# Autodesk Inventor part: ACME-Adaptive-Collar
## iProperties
Company: ACME-Hardware
Shininess: 64.0
Length Units: 11269
Angle Units: 11279
Time Units: 11290
Mass Units: 11283
Length Display Precision: 3
Angle Display Precision: 2
Compacted: True
Part Number: ACME-Adaptive-Collar
Document SubType Name: Modeling
Created: 2003-12
Catalog Web Link: www.autodesk.com
Vendor: Autodesk, Inc.
Designer: Administrator
Manufacturer: Standard
Standards Organization: Custom
Density: 1 g/cm^3
Mass: 2.12058 g
Surface Area: 19.3208 cm^2
Volume: 2.12058 cm^3
Density: 0.0
Volumn: 0.0
Area: 0.0
PropertySet Name: Model Information
Control State: 0
Master: False
Checked Out: False
Author: Administrator
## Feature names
1. Extrusion1
